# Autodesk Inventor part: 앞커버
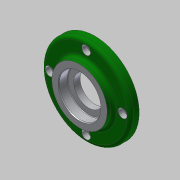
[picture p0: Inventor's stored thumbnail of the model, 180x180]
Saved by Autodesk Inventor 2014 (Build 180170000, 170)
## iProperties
Created: 2019-01
Part Number: 앞커버
Material: 알루미늄 6061
Document SubType Name: Modeling
Designer: mduedu
Density: 1 g/cm^3
Appearance: 알루미늄 - 평지
Author: mduedu
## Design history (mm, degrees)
sketch "스케치1"
  geometry: L1 (0, 0)-(6, 0); L2 (6, 0)-(6, 25); L3 (6, 25)-(0, 25); L4 (0, 25)-(0, 0); L5 (6, 0)-(14, 0); L6 (14, 0)-(14, 40); L7 (14, 40)-(6, 40); L8 (6, 40)-(6, 0); L9 (14, 0)-(19, 0); L10 (19, 0)-(19, 26); L11 (19, 26)-(14, 26); L12 (14, 26)-(14, 0)
  constraints: 24 end point, 6 parallel, 3 horizontal, 3 perpendicular
  dimensions: "d6" = 80 diameter of L7 L5; "d8" = 50 diameter of L3 L1; "d9" = 52 diameter of L11 L9; "d10" = 5 distance of L10.end L11.end; "d11" = 6 distance of L2.end L3.end; "d12" = 19 distance between parallel lines of L4 L10; "d13" = 8 distance of L6.end L7.end (derived)
revolve "회전1" sketch "스케치1" stored, may be unused: angle "d5" = 90 deg
sketch "스케치2"
  geometry: C1 r 13.5 at (0, 0); 1 further point
  constraints: 1 centre point, 1 coincident
  dimensions: "d14" = 27 diameter of C1
extrude "돌출1" cut sketch "스케치2" stored distance "d15" = 10; taper "d16" = 0 deg
sketch "스케치3" dims "d17" = 66
  geometry: 6 further points
  constraints: 2 vertical alignment, 1 coincident, 7 other
  dimensions: "d20" = 360 deg dimension on point (0, 0) point (0, 33) (derived)
sketch "스케치4"
  geometry: 4 further points
  constraints: 4 other
hole "구멍1" sketch "스케치4" at (-33, 0), (0, -33), (33, 0), (0, 33) diameter "d22" = 4.5; stored, may be unused: countersink angle "d26" = 90 deg, drill point angle "d28" = 0 deg; dims "d23" = 6, "d24" = 8, "d25" = 4.6, "d27" = 8
fillet "모깎기1" dims "d29" = 3
sketch "스케치5"
  geometry: C1 r 19 at (0, 0); 1 further point
  constraints: 1 centre point, 1 coincident
  dimensions: "d30" = 38 diameter of C1
extrude "돌출2" cut sketch "스케치5" distance "d31" = 8.3; taper "d32" = 0 deg
fillet "모깎기2" dims "d33" = 3
chamfer "모따기1" distance "d34" = 0.8; stored, may be unused: second distance "d35" = 2, angle "d36" = 30 deg
fillet "모깎기3" dims "d37" = 0.5
sketch "스케치6"
  geometry: C1 r 22 at (0, 0); 1 further point
  constraints: 1 centre point, 1 coincident
  dimensions: "d38" = 44 diameter of C1
extrude "돌출3" cut sketch "스케치6" distance "d39" = 5; taper "d40" = 0 deg
fillet "모깎기4" dims "d41" = 3
chamfer "모따기2" distance "d42" = 1; stored, may be unused: second distance "d43" = 2, angle "d44" = 30 deg
node "솔리드1"
